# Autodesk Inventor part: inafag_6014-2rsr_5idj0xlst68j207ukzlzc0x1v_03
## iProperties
Shininess: 64.0
Angle Display Precision: 2
Document Length Units: 11269
Document Angle Units: 11279
Document Time Units: 11290
Document Mass Units: 11283
Document Length Units Precision: 3
Document Angle Units Precision: 2
Compacted: True
Created: 2008-08
Part Number: inafag_6014-2rsr_5idj0xlst68j207ukzlzc0x1v_03
Document SubType Name: Modeling
Designer: tpomodeler
Density: 0.0
Volumn: 0.0
Area: 0.0
PropertySet Name: Model Information
Control State: 0
Master: False
Checked Out: False
Author: tpomodeler
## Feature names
1. inafag_6014-2rsr_5idj0xlst68j207ukzlzc0x1v
